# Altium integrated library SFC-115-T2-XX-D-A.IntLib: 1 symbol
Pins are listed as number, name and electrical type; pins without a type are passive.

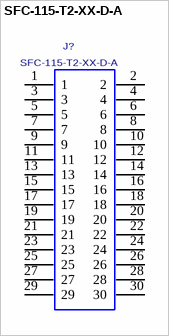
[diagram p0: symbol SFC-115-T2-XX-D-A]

## SFC-115-T2-XX-D-A
designator J?
.050" x .050" Socket Strip Double Row Assembly; MANUFACTURER: SAMTEC
footprint SFC-115-T2-XX-D-A
pins: 1, 2, 3, 4, 5, 6, 7, 8, 9, 10, 11, 12, 13, 14, 15, 16, 17, 18, 19, 20, 21, 22, 23, 24, 25, 26, 27, 28, 29, 30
